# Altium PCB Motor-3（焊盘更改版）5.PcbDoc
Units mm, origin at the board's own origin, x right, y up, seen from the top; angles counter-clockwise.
Board outline 35.05 x 35.13 mm, 4 copper layers (Top1, Signal2, Gnd3, Bottom4), stack 0.778 mm thick; 73 components, 65 nets, 252 pads, 128 vias.
Unrouted connection lines stored in the file: 54.
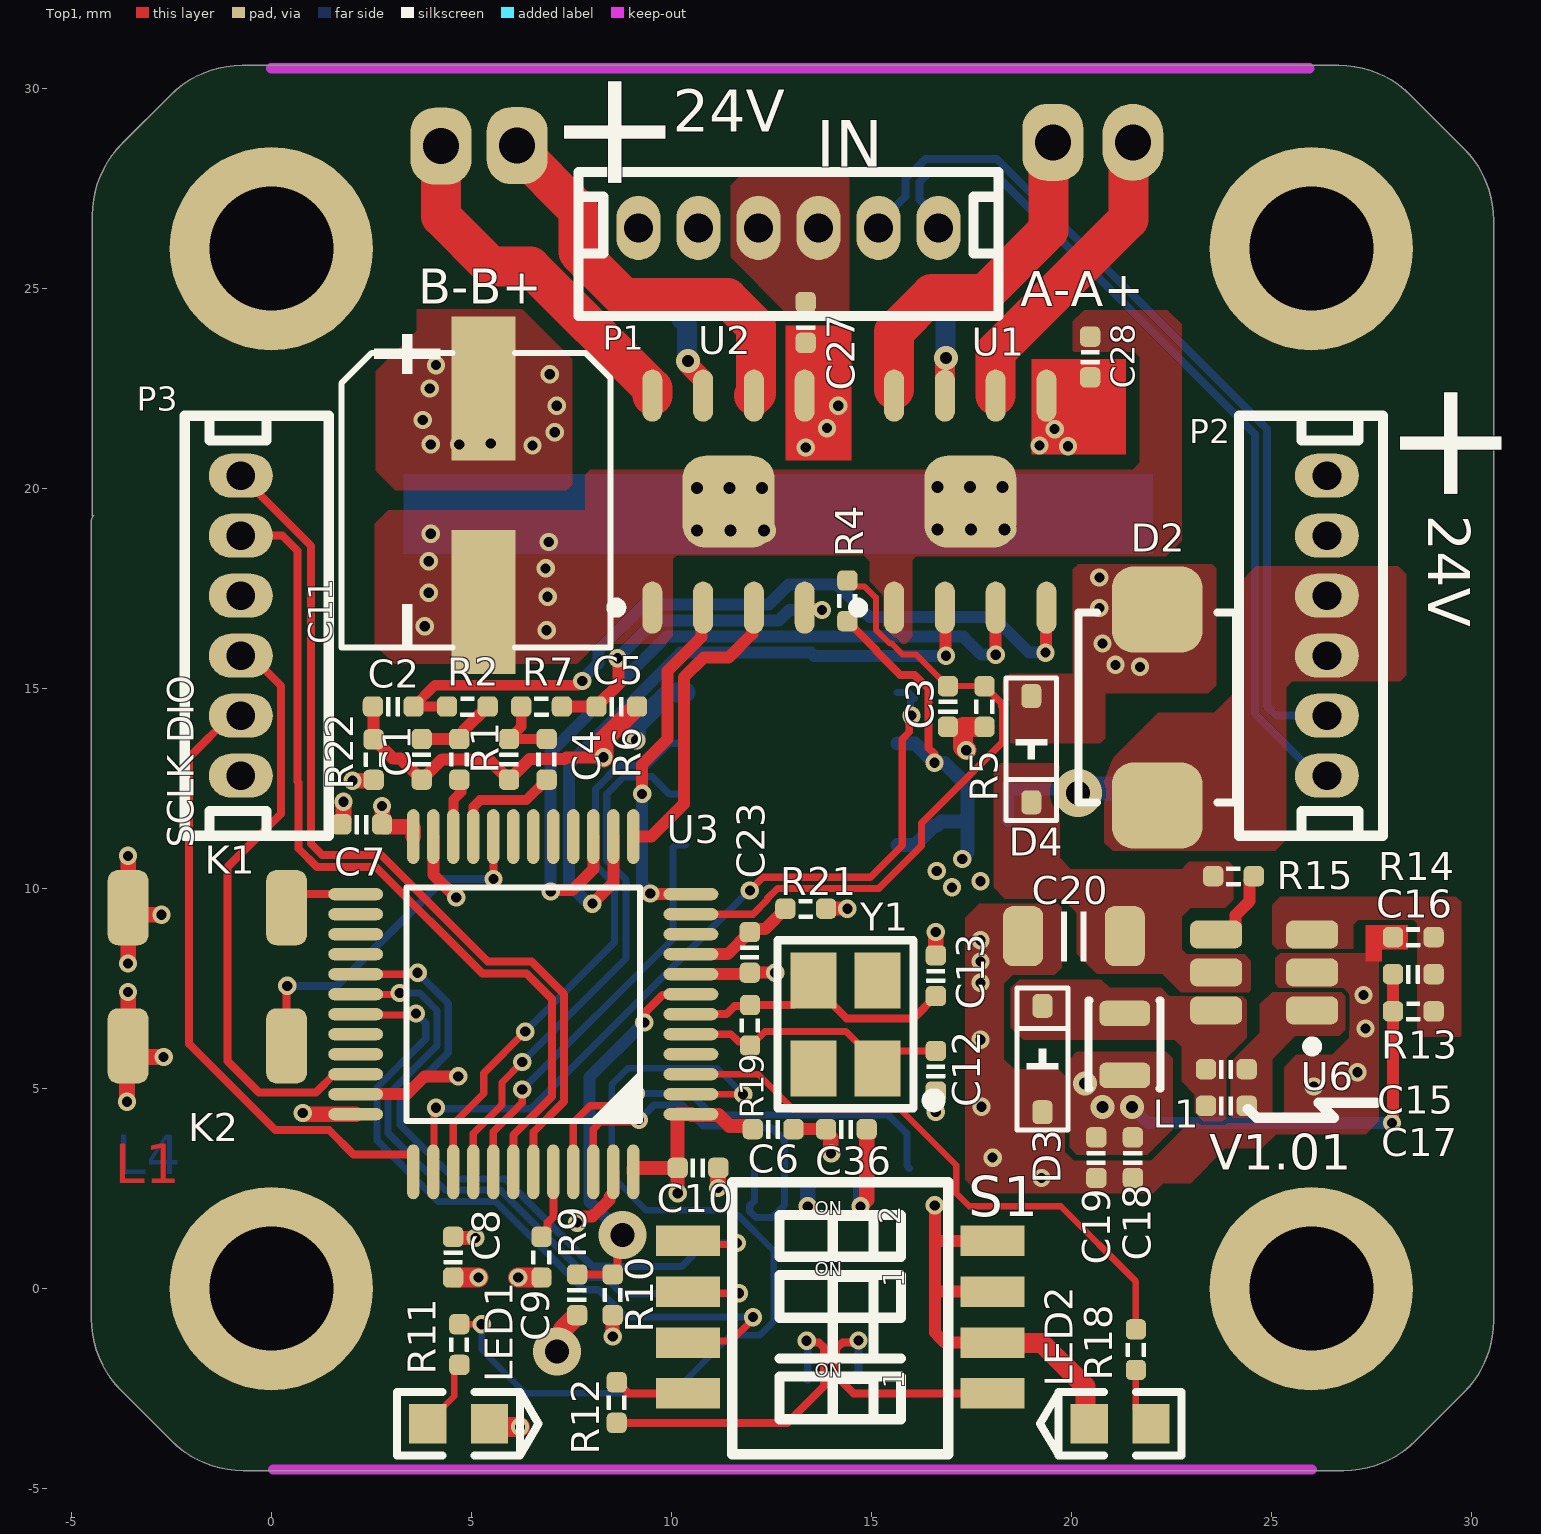
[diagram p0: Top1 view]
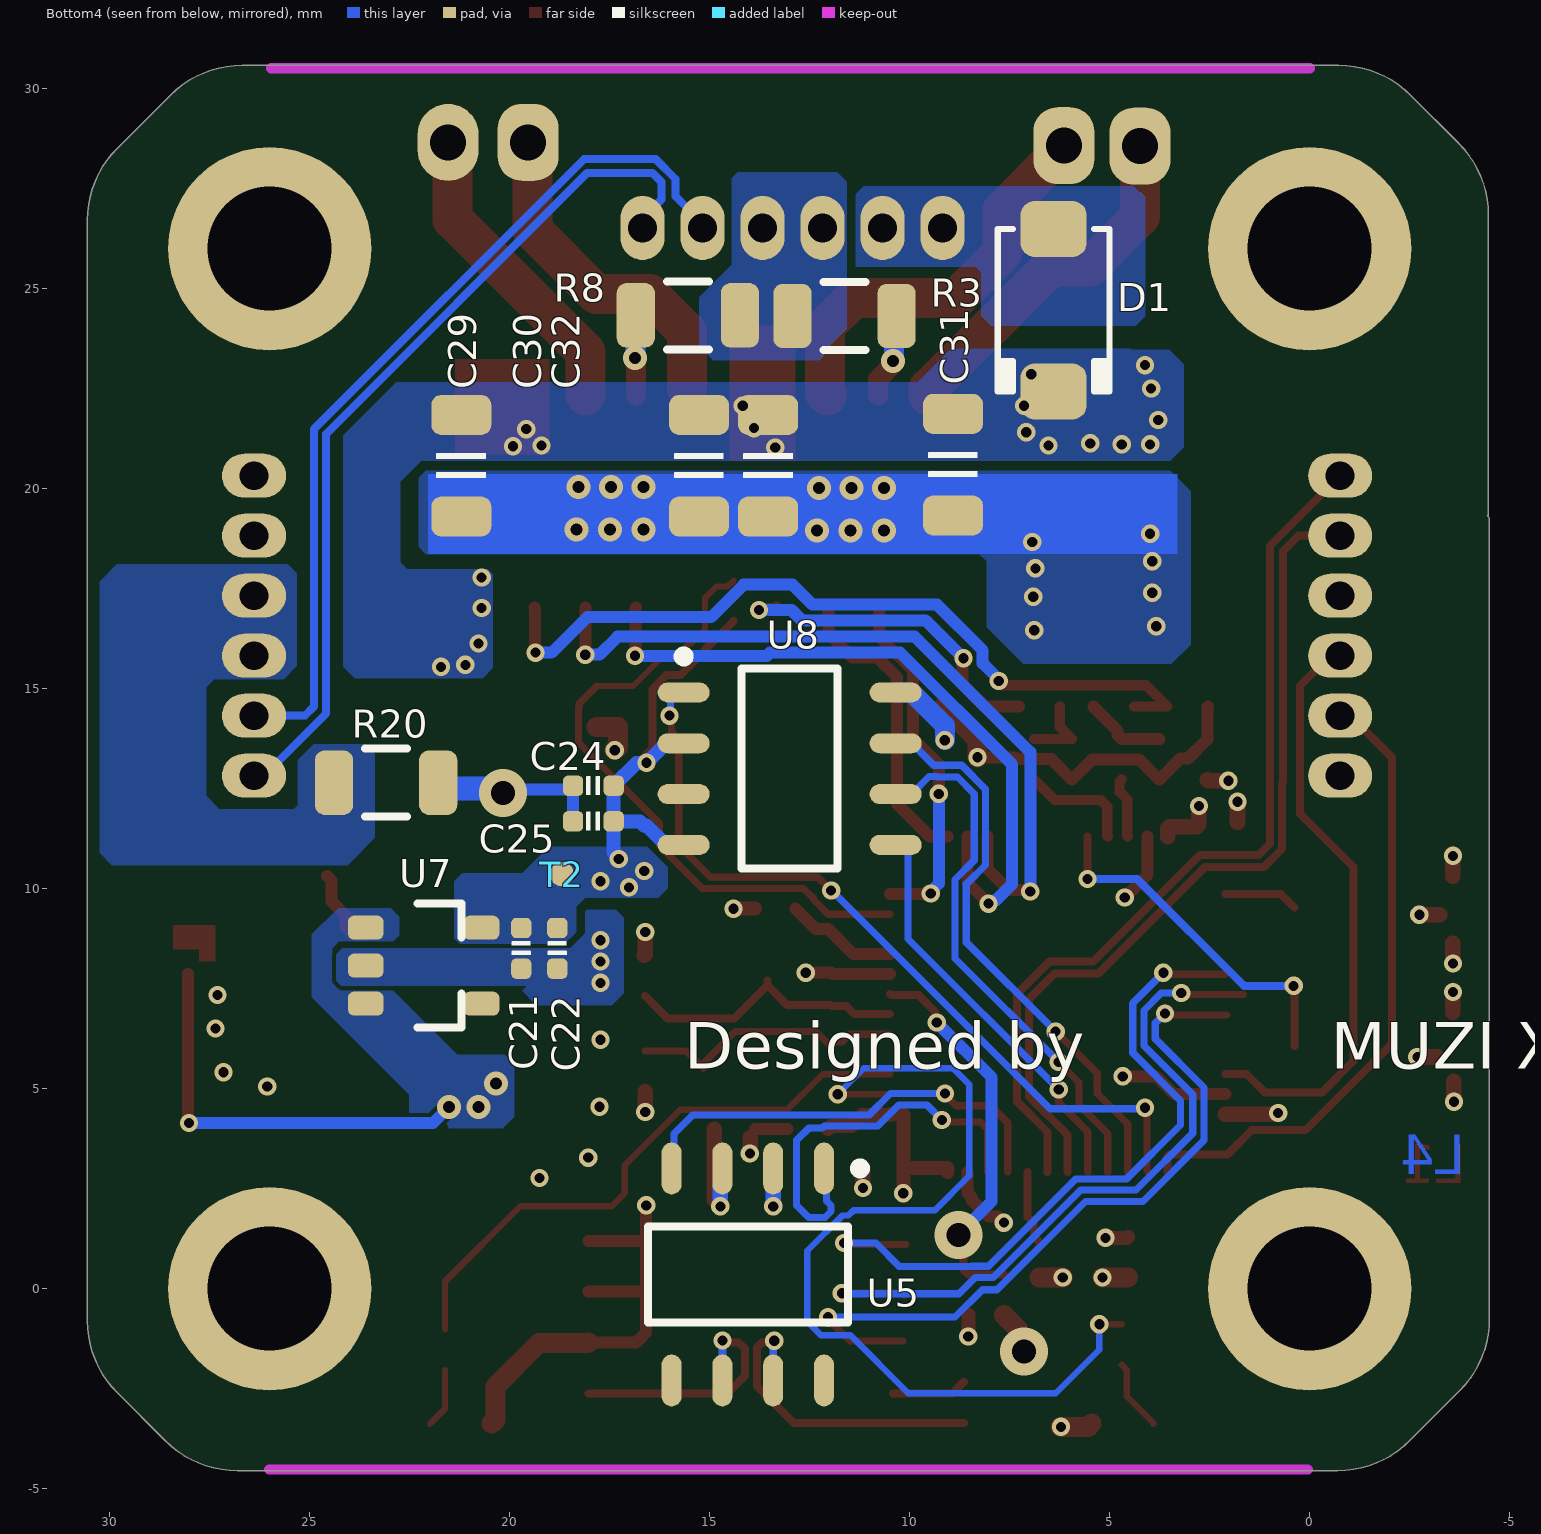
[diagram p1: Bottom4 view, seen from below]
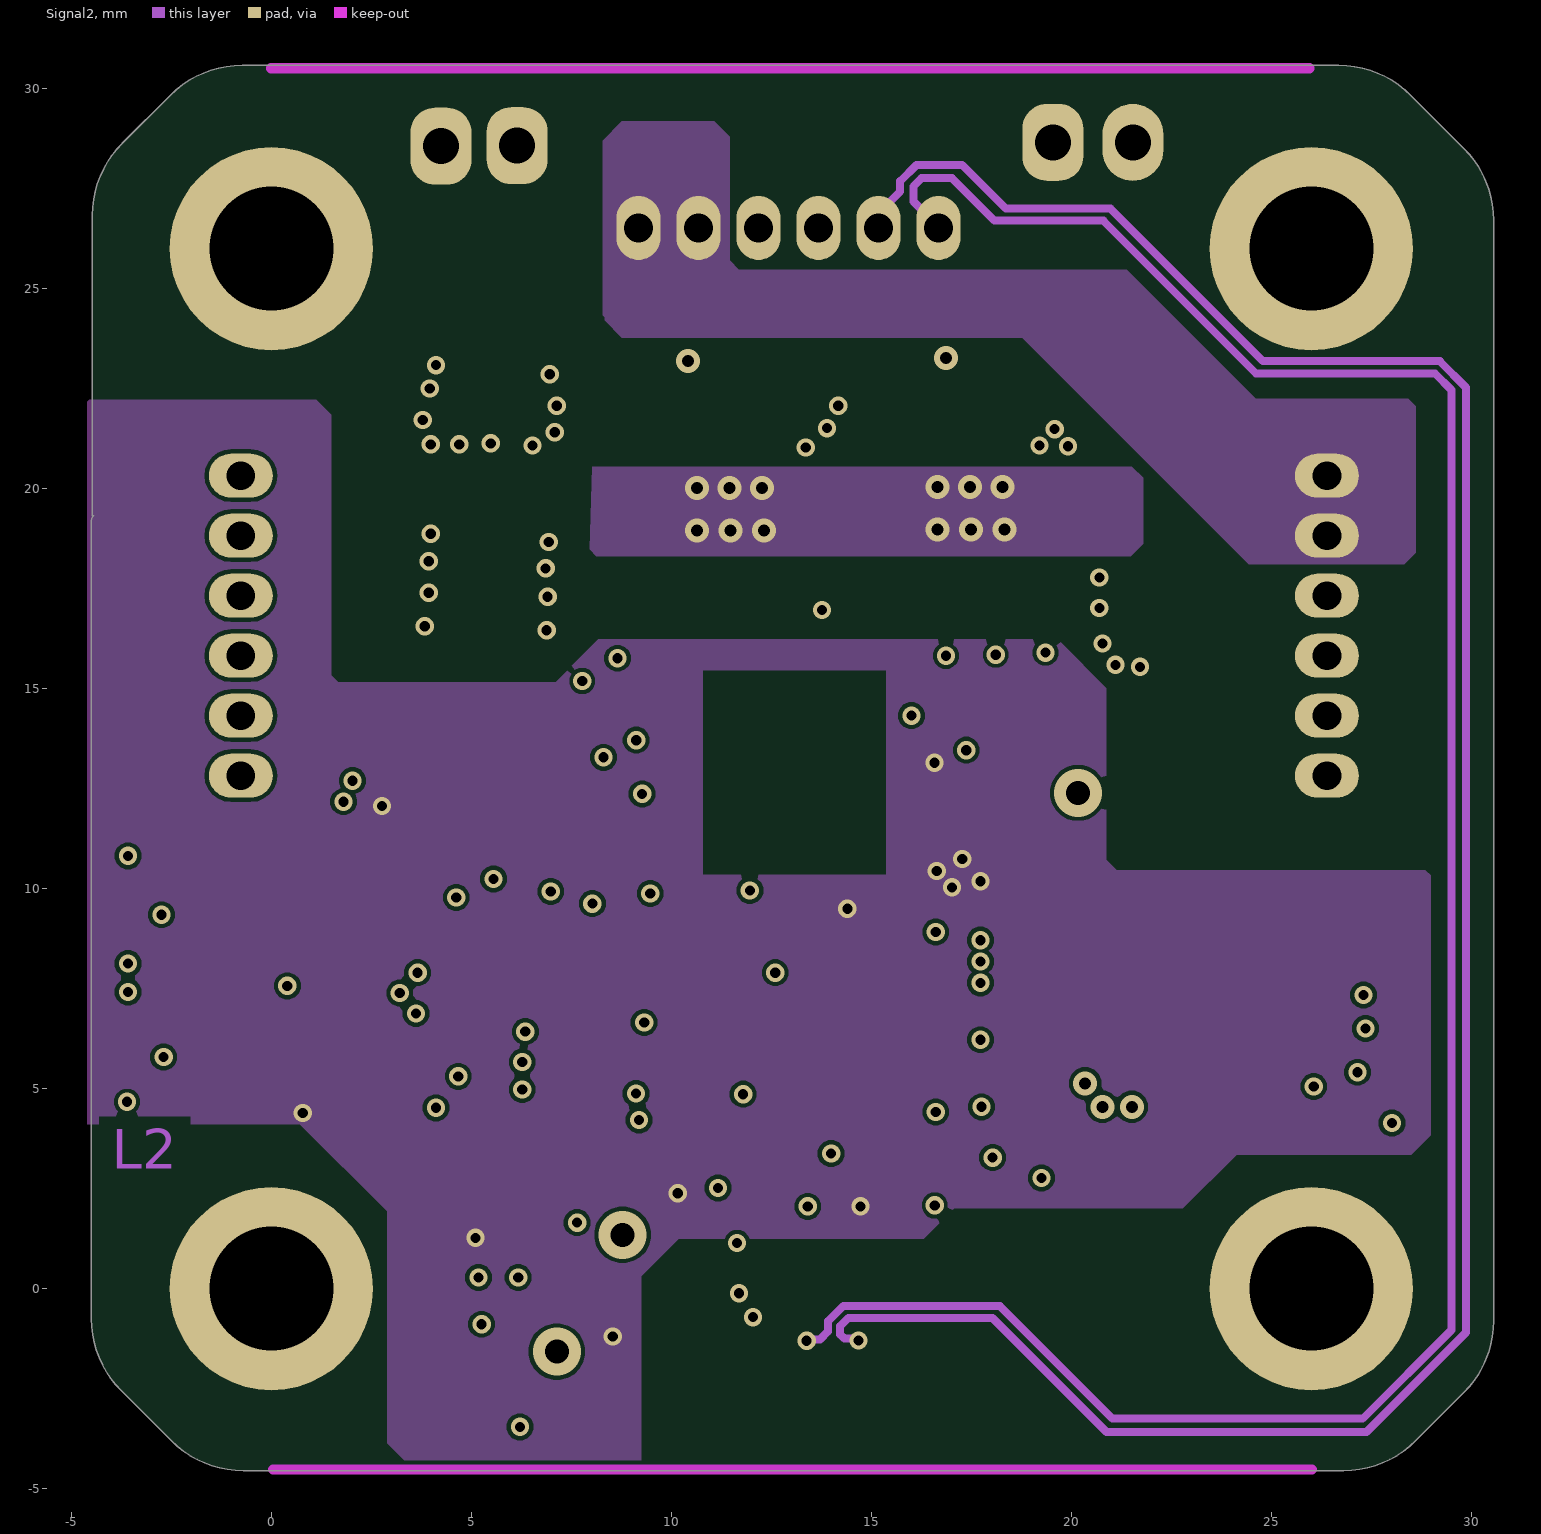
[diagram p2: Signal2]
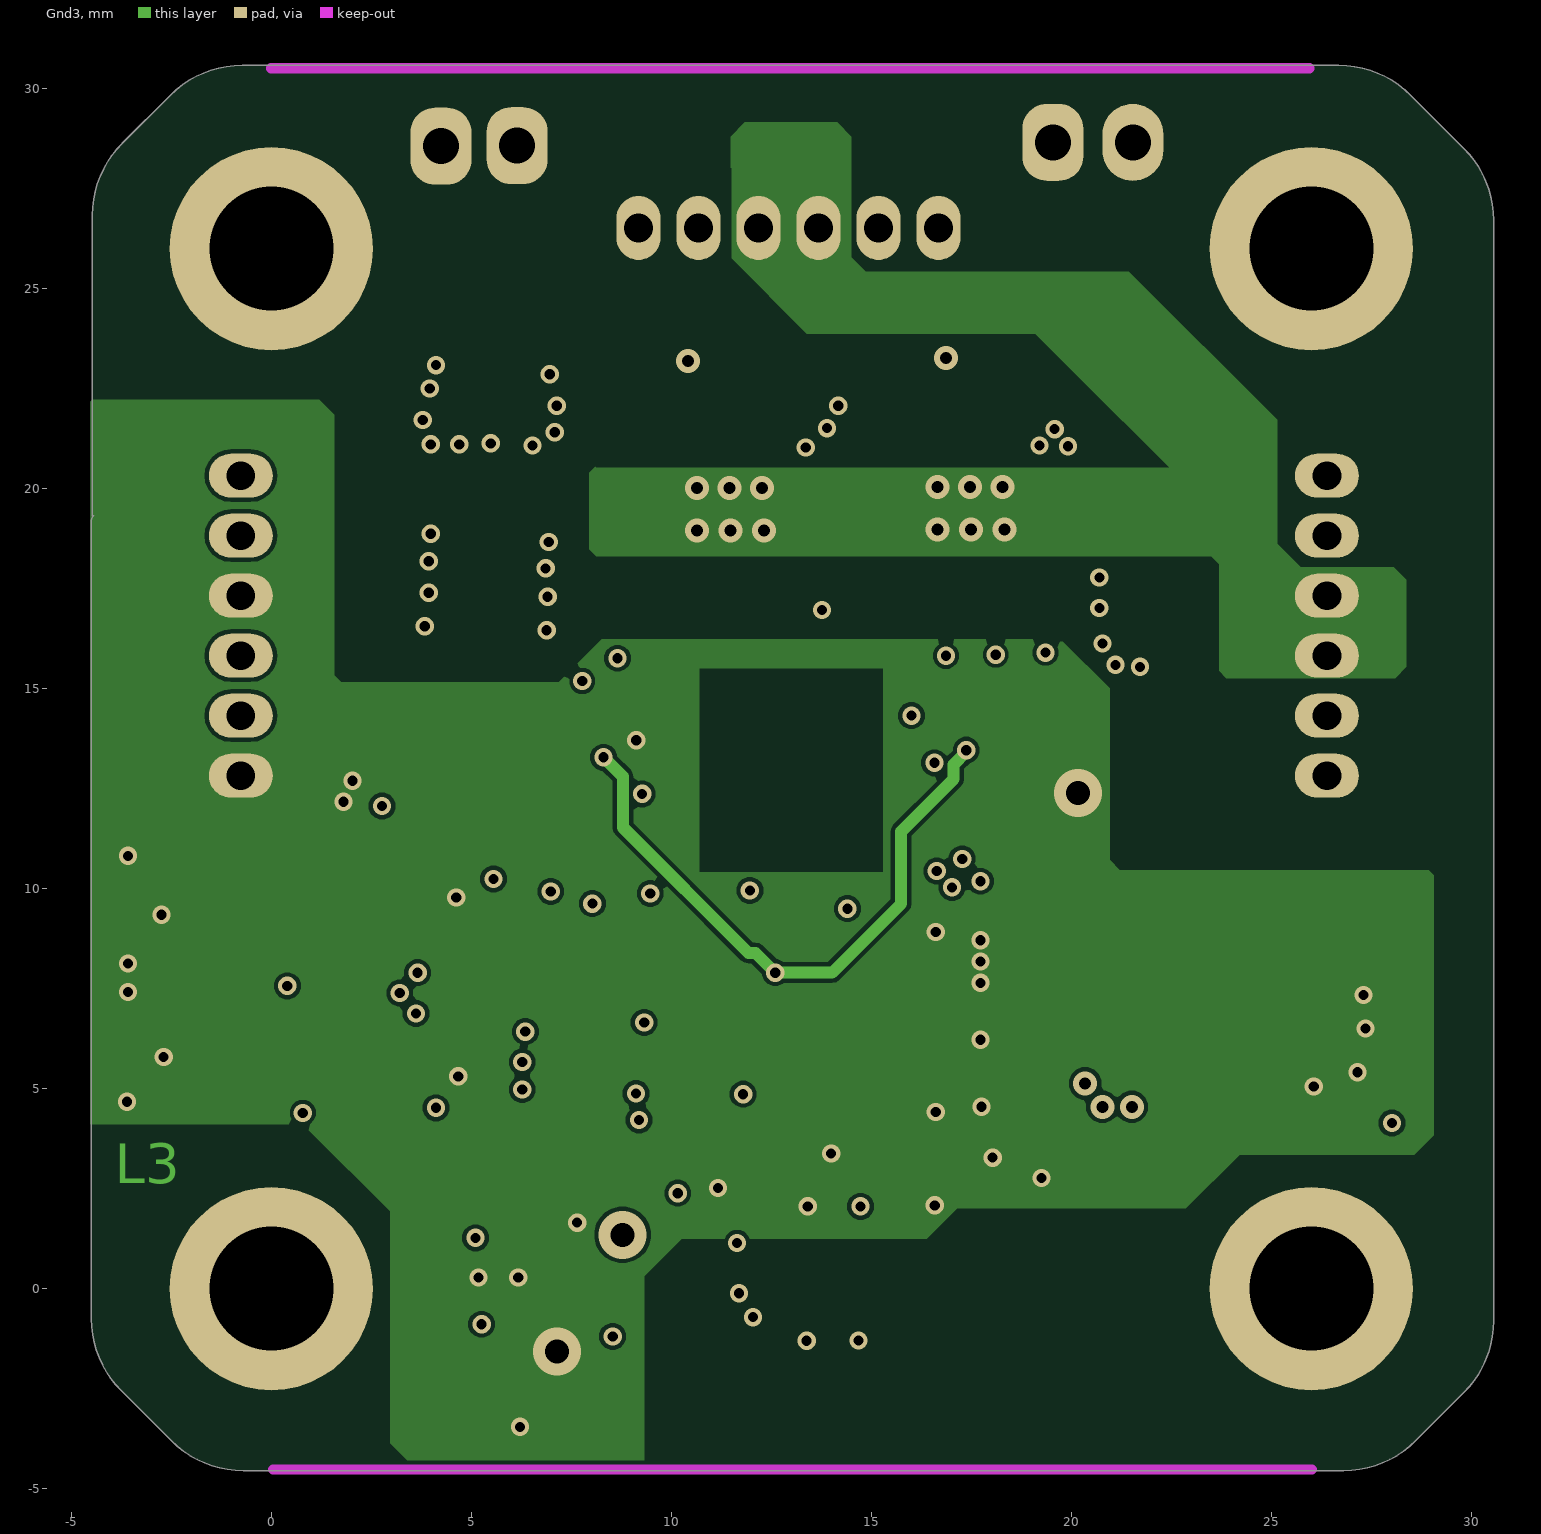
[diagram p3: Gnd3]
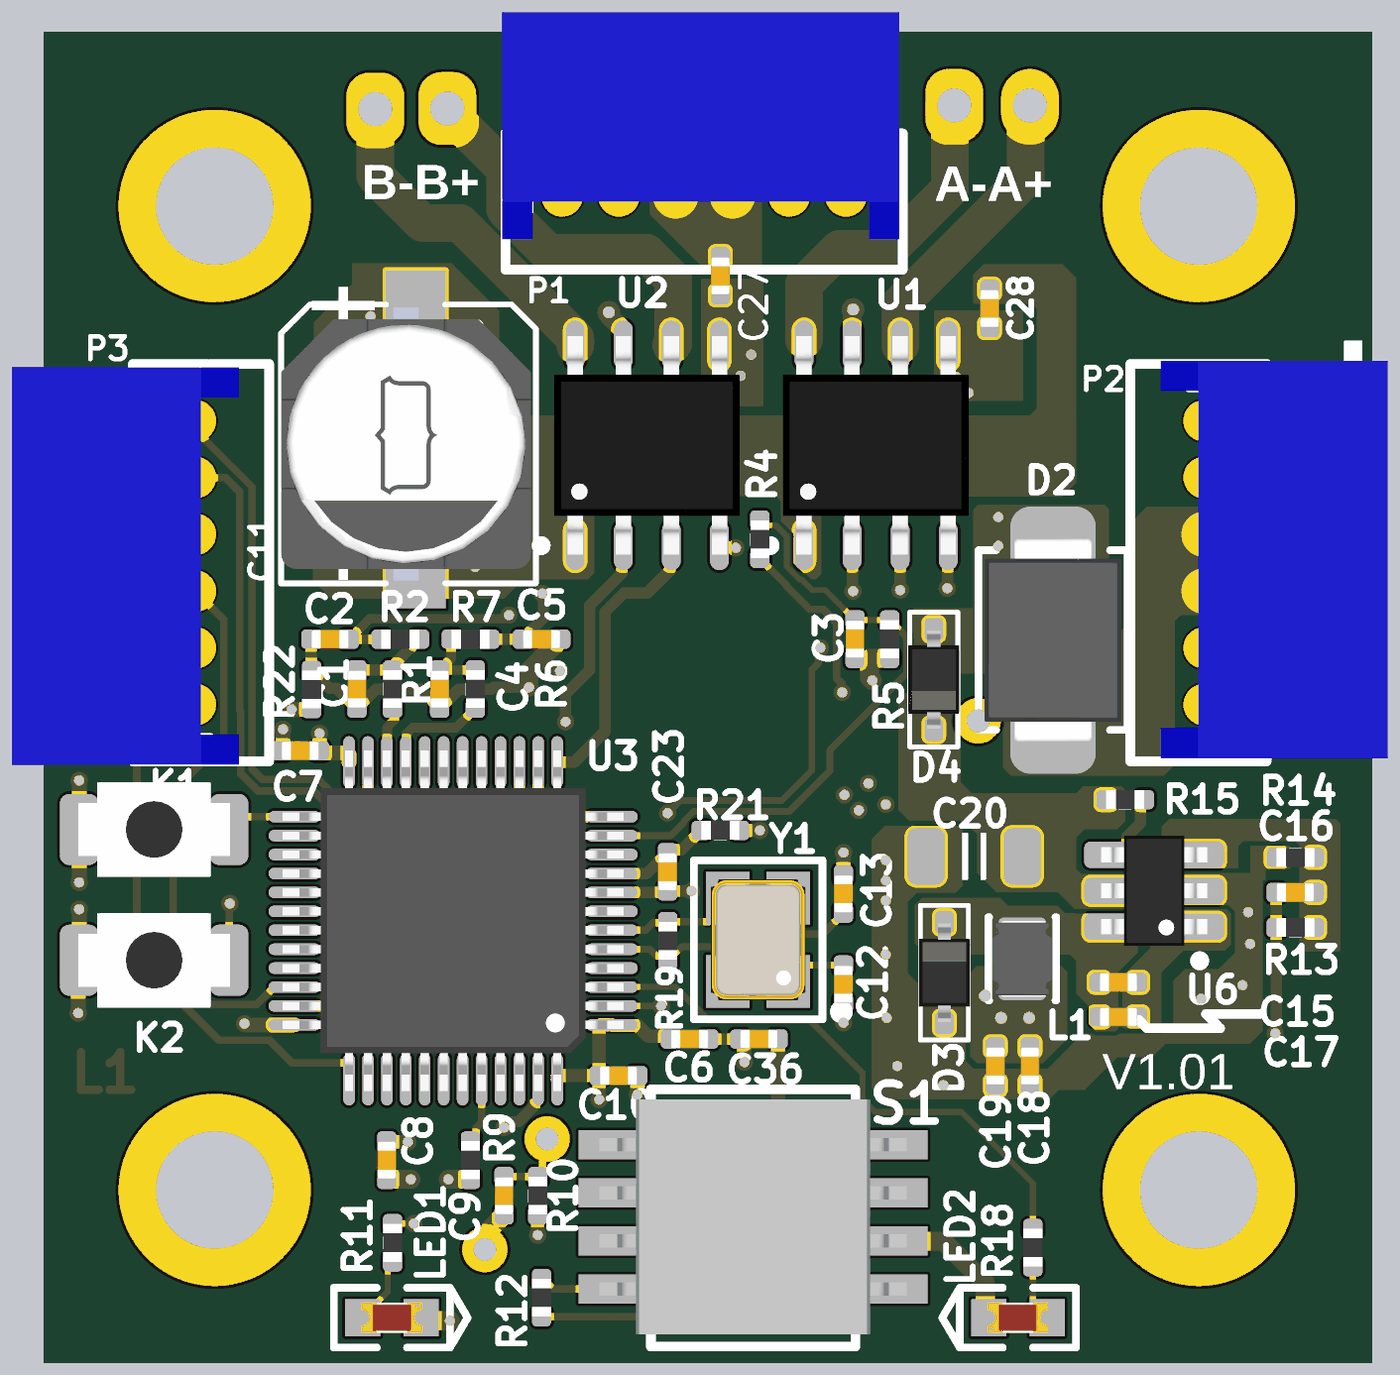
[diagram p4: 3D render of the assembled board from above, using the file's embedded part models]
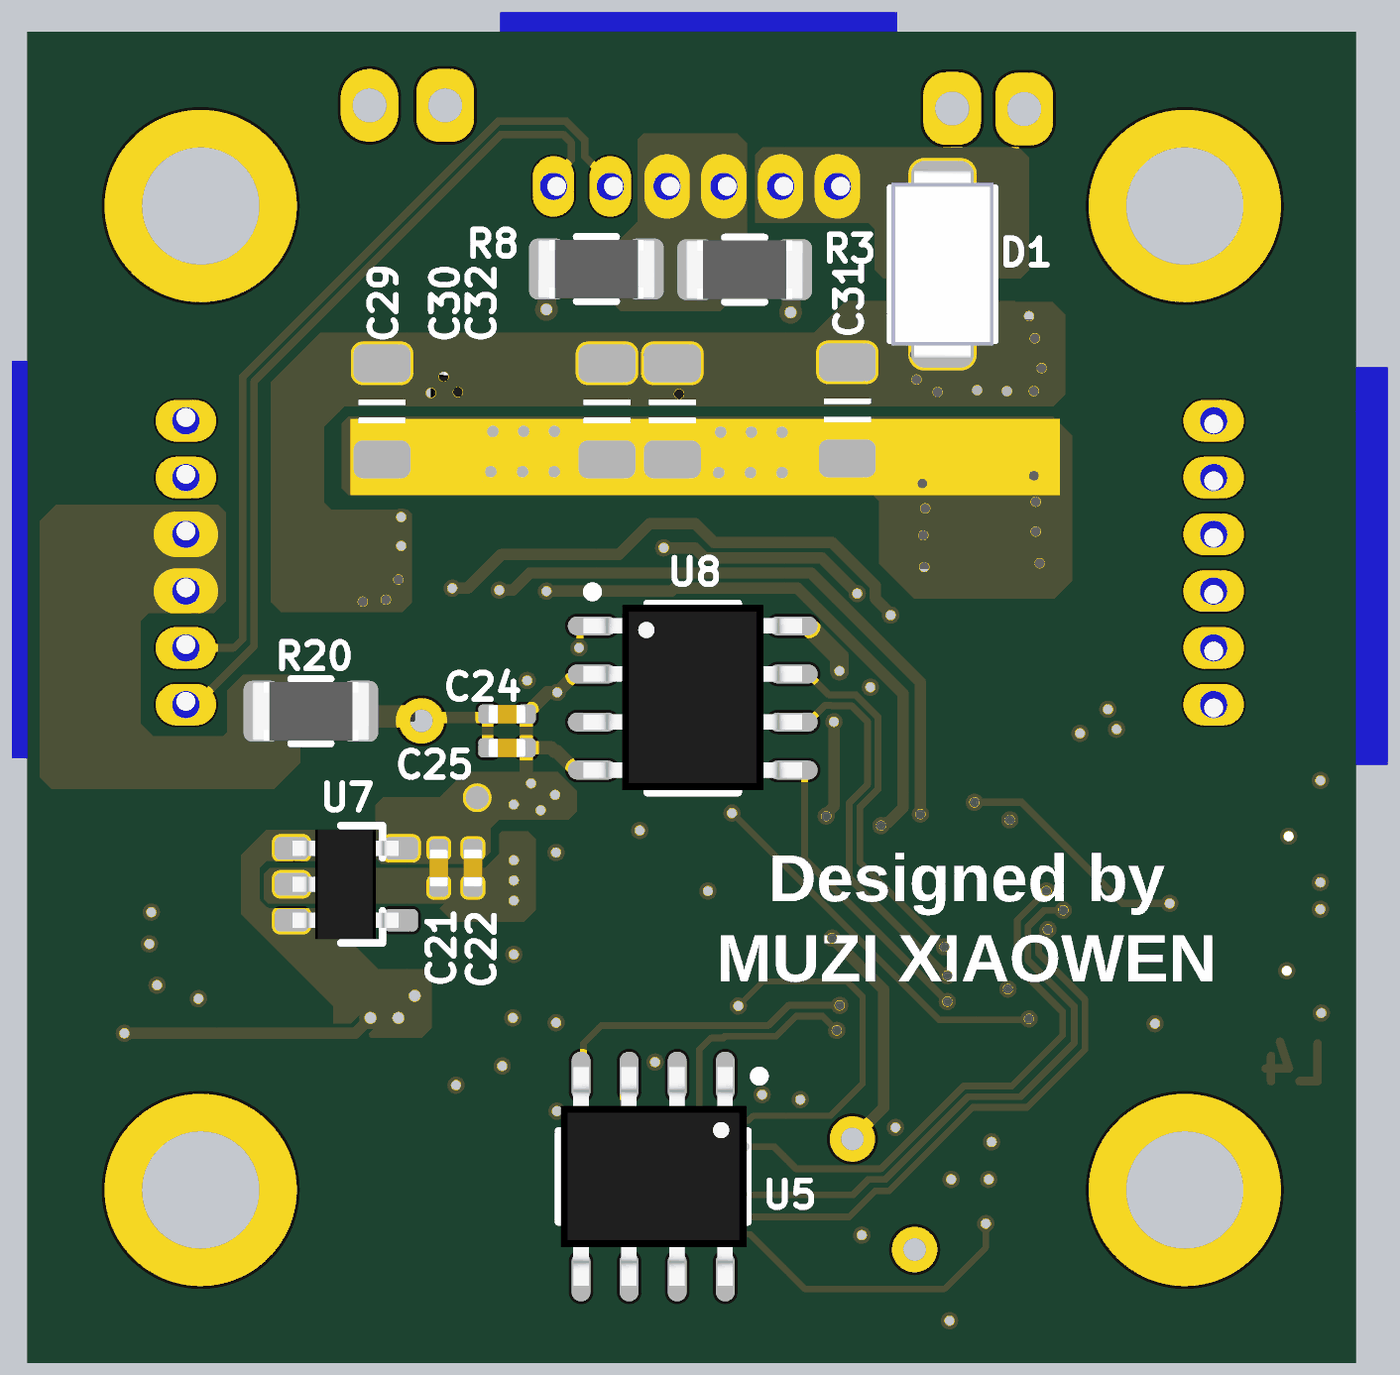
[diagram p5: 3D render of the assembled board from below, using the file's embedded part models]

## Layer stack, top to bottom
Top Solder: solder mask 0.0102, Solder Resist, Dk 3.5
Top1: signal copper 0.0356
Dielectric1: core 0.254, FR-4, Dk 4.2
Signal2: signal copper 0.036
Dielectric2: core 0.254, Dk 4.2
Gnd3: signal copper 0.036
Dielectric3: prepreg 0.127, Dk 4.2
Bottom4: signal copper 0.0356
Bottom Solder: solder mask 0.0102, Solder Resist, Dk 3.5

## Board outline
-4.47,19.329 -4.47,26.837 cw(c-1.93,26.837) -3.726,28.633 -2.522,29.838 cw(c-0.726,28.042) -0.726,30.582 26.685,30.582 cw(c26.685,28.042) 28.481,29.838 29.812,28.506 cw(c28.016,26.71) 30.556,26.71 30.556,-0.802 cw(c28.016,-0.802) 29.812,-2.598 28.608,-3.803 cw(c26.812,-2.007) 26.812,-4.547 -0.7,-4.547 cw(c-0.7,-2.007) -2.497,-3.803 -3.752,-2.547 cw(c-1.956,-0.751) -4.496,-0.751 -4.496,19.207 cw(c-4.322,19.207) -4.445,19.329

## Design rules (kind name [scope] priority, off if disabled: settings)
Clearance [All] p1: gap=0.102 ignorepadtopadclearanceinfootprint=FALSE except(0: Arc-Hole Track-Hole SMDPad-Hole THPad-Hole Via-Hole Fill-Hole Poly-Hole Region-Hole Text-Hole)
ComponentClearance [All] p1: gap=0 collisioncheckmode=3 verticalgap=0 showdistances=FALSE
DiffPairsRouting [All] p1: maxlimit=0.229 minlimit=0.229 mostfreqgap=0.229 toplayer_minwidth=0.381 toplayer_maxwidth=0.381 toplayer_prefwidth=0.381 midlayer1_minwidth=0.381 midlayer1_maxwidth=0.381 midlayer1_prefwidth=0.381 midlayer2_minwidth=0.381 midlayer2_maxwidth=0.381 midlayer2_prefwidth=0.381 bottomlayer_minwidth=0.381 bottomlayer_maxwidth=0.381 bottomlayer_prefwidth=0.381 maxuncoupledlength=12.7
FanoutControl Fanout_BGA [All] p1: bgadir=Out bgaviamode=Centered fanoutstyle=Auto fanoutdirection=Alternating viagrid=0.025 // Fanout_BGA (Default Rule)
HoleSize [All] p1: absolutevalues=TRUE maxlimit=254 minlimit=0.203 maxpercent=80.000 minpercent=20.000
MinimumSolderMaskSliver [All] p1 off: minsoldermaskwidth=0.051
PlaneClearance [All] p1: clearance=0.203
PlaneConnect [All] p1: planeconnectstyle=Direct reliefexpansion=0.508 reliefentries=4 reliefconductorwidth=0.254 reliefairgap=0.254
PolygonConnect [All] p1: connectstyle=Direct reliefconductorwidth=0.254 reliefentries=4 polygonreliefangle="90 Angle" airgapwidth=0.254
RoomDefinition Port [InComponentClass('Port')] p1 off: confinementstyle=ConfineIn formatcopy=TRUE lockcomponents=FALSE outline -13.335,-36.017 37.465,-36.017 37.465,-10.617 -13.335,-10.617
RoomDefinition MCU [InComponentClass('MCU')] p2 off: confinementstyle=ConfineIn formatcopy=TRUE lockcomponents=FALSE outline -13.233,-36.17 37.567,-36.17 37.567,-10.77 -13.233,-10.77
RoomDefinition Interface [InComponentClass('Interface')] p3 off: confinementstyle=ConfineIn formatcopy=TRUE lockcomponents=FALSE outline -14.453,-36.5 36.347,-36.5 36.347,-11.1 -14.453,-11.1
RoomDefinition Drive [InComponentClass('Drive')] p4 off: confinementstyle=ConfineIn formatcopy=TRUE lockcomponents=FALSE outline -13.005,-36.5 37.795,-36.5 37.795,-11.1 -13.005,-11.1
RoomDefinition Power [InComponentClass('Power')] p5 off: confinementstyle=ConfineIn formatcopy=TRUE lockcomponents=FALSE outline -12.675,-36.144 38.125,-36.144 38.125,-10.744 -12.675,-10.744
RoutingVias [All] p1: holewidth=0.203 width=0.406 viastyle="Through Hole" minholewidth=0.152 minwidth=0.305 maxholewidth=0.711 maxwidth=1.27
SilkToSilkClearance [All] p1: silktosilkclearance=0
SilkToSolderMaskClearance [IsPad] p1: minsilkscreentomaskgap=0 clearancetoexposedcopper=TRUE
SolderMaskExpansion [All] p1: expansion=0.076 istentingtop=FALSE
Width GND [(InNet('AGND') OR InNet('GND'))] p1: maxlimit=1.27 minlimit=0.102 preferedwidth=0.254
Width VCC [(InNet('VDD_SYS_3.3V') OR InNet('VDD_AV_3.3V') OR InNet('VDD_5V') OR InNet('VDD1V2-SYS') OR InNet('VDD1V1-EPHY') OR InNet('VDD-CPUX') OR InNet('VDD-CPUS') OR InNet('VDD-CPUFB') OR InNet('VCC-DRAM'))] p2: maxlimit=1.27 minlimit=0.102 preferedwidth=0.254
Width [All] p3: maxlimit=254 minlimit=0.102 preferedwidth=0.102
21 further rules are at their usual default settings.

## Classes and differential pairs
component class Port: C36 K1 K2 P1 P2 P3 R12 S1 U5
component class MCU: C6 C7 C8 C9 C10 C12 C13 C23 LED1 LED2 R9 R10 R11 R18 R19 R21 R22 U3 Y1
component class Interface: C24 C25 U8
component class Drive: C1 C2 C3 C4 C5 C27 C28 R1 R2 R3 R4 R5 R6 R7 R8 R20 U1 U2
component class Power: C11 C15 C16 C17 C18 C19 C20 C21 C22 C29 C30 C31 C32 D1 D2 D3 D4 L1 R13 R14 R15 T2 U6 U7

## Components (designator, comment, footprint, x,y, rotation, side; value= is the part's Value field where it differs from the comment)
C1 "0.1uF" CAP_0402 3.759,13.233 r90 top value=0.1u
C2 "0.1uF" CAP_0402 3.048,14.554 r0 top value=0.1u
C3 "10uF" CAP_0402 16.916,14.554 r90 top value=0.1u
C4 "0.1uF" CAP_0402 5.944,13.233 r90 top value=0.1u
C5 "0.1uF" CAP_0402 8.636,14.554 r180 top value=0.1u
C6 "0.1uF" CAP_0402 12.548,3.988 r180 top value=0.1u
C7 "0.1uF" CAP_0402 2.261,11.608 r0 top value=0.1u
C8 "0.1uF" CAP_0402 4.547,0.787 r90 top value=0.1u
C9 "0.1uF" CAP_0402 7.645,-0.152 r90 top value=0.1u
C10 "10uF" CAP_0402 10.668,3.023 r180 top value=0.1u
C11 "220uF/25V" CAP-SMD_BD8.0-L8.3-W8.3-LS9.3-FD 5.309,19.964 r270 top locked value=150uF/35V
C12 "20pF" CAP_0402 16.612,5.436 r270 top
C13 "20pF" CAP_0402 16.612,7.823 r90 top
C15 "0.1uF" CAP_0402 23.876,5.486 r0 top value=0.1u
C16 "100pF" CAP_0402 28.55,7.861 r0 top value=0.1u
C17 "0.1uF" CAP_0402 23.876,4.572 r0 top value=0.1u
C18 "0.1uF" CAP_0402 21.539,3.277 r90 top value=0.1u
C19 "10uF" CAP_0402 20.625,3.277 r90 top value=0.1u
C20 "10uF/50V" 1206-CAP 20.066,8.814 r0 top value=0.1u
C21 "0.1uF" CAP_0402 19.71,8.509 r90 bottom value=0.1u
C22 "10uF" CAP_0402 18.809,8.509 r90 bottom value=0.1u
C23 "0.1uF" CAP_0402 11.963,8.407 r90 top value=0.1u
C24 "10uF" CAP_0402 17.907,12.573 r180 bottom value=0.1u
C25 "0.1uF" CAP_0402 17.907,11.684 r180 bottom value=0.1u
C27 "0.1uF" CAP_0402 13.36,24.155 r270 top value=0.1u
C28 "0.1uF" CAP_0402 20.472,23.292 r270 top value=0.1u
C29 "10uF/50V" 1206-CAP 21.209,20.574 r270 bottom
C30 "10uF/50V" 1206-CAP 15.265,20.574 r270 bottom
C31 "10uF/50V" 1206-CAP 8.915,20.599 r270 bottom
C32 "10uF/50V" 1206-CAP 13.538,20.574 r270 bottom
C36 "0.1uF" CAP_0402 14.376,3.988 r0 top value=0.1u
D1 "SS54" DO-214AC 6.401,24.46 r270 bottom
D2 "SMBJ28CA" SMBJ-CA_MFG 22.149,14.529 r90 top
D3 "二极管-5819W" SOD-323 19.279,5.74 r90 top
D4 "二极管-5819W" SOD-323 18.999,13.487 r270 top
K1 "TACT 2P" ButtonTACT_3x4x2_180 -1.6,9.525 r0 top value=3x4
K2 "TACT 2P" ButtonTACT_3x4x2_180 -1.6,6.071 r0 top value=3x4
L1 "6.8uH" IND-201612 21.336,6.108 r270 top
LED1 "LED GREEN" LED-0603 4.693,-3.423 r180 top
LED2 "LED GREEN" LED-0603 21.209,-3.327 r0 top
P1 "Header 6H" CONN-TH_HC-ZH1.5-6A-s 12.929,26.518 r0 top locked
P2 "Header 6H" CONN-TH_HC-ZH1.5-6A-s 26.391,16.574 r270 top
P3 "Header 6H" CONN-TH_HC-ZH1.5-6A-s -0.762,16.574 r90 top
R1 "1K" RES_0402 4.699,13.233 r90 top value=22R
R2 "1K" RES_0402 4.902,14.554 r180 top value=22R
R3 "0.1R" 1206-RES 15.545,24.333 r180 bottom value=22R
R4 "NCP15XH103F03RC" RES_0402 14.402,17.196 r270 top value=10k
R5 "3.3K" RES_0402 17.831,14.554 r90 top value=22R
R6 "1K" RES_0402 6.883,13.233 r90 top value=22R
R7 "1K" RES_0402 6.756,14.554 r0 top value=22R
R8 "0.1R" 1206-RES 11.627,24.318 r0 bottom value=22R
R9 "10K" RES_0402 6.756,0.787 r270 top value=22R
R10 "10K" RES_0402 8.534,-0.152 r270 top value=22R
R11 "1K" RES_0402 4.699,-1.397 r270 top value=22R
R12 "120R" RES_0402 8.636,-2.845 r90 top value=22R
R13 "10K" RES_0402 28.55,6.934 r180 top value=22R
R14 "1.8K" RES_0402 28.55,8.788 r0 top value=22R
R15 "1M" RES_0402 24.054,10.312 r0 top value=22R
R18 "1K" RES_0402 21.615,-1.524 r270 top value=22R
R19 "1M" RES_0402 11.969,6.585 r270 top value=22R
R20 "0R" 1206-RES 23.089,12.649 r0 bottom
R21 "0" RES_0402 13.36,9.5 r0 top value=0R
R22 "0" RES_0402 2.559,13.227 r90 top value=0R
S1 "DSHP04TSGER" SW-SMD_DSHP04TS-S 10.414,-0.076 r90 top
T2 "测试点" TEST_PT 18.694,10.363 r90 bottom
U1 "TB67H450FNG" SO-8-PAD 17.475,19.677 r0 top locked
U2 "TB67H450FNG" SO-8-PAD 11.43,19.677 r0 top locked
U3 "STM32F103CBT6" LQFP-48 6.299,7.112 r0 top locked
U5 "SN65HVD232D" so-8 14.046,0.356 r90 bottom
U6 "ME3116" SOT23-6 24.822,7.905 r90 top
U7 "LP2992 3V3" SOT23-5 22.098,8.077 r270 bottom
U8 "MT6816" SO-8 13,13 r180 bottom locked
Y1 "XTAL-4" LC-SMD-3225_4P 14.357,6.61 r90 top locked value="12 MHz"

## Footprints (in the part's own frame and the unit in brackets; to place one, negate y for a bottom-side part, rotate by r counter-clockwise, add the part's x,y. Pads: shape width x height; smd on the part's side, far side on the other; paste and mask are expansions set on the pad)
1206-CAP [mm]
  rrect50% 1x1.5 smd: 1(-1.27,0) 2(1.27,0)
  silkscreen extent -0.3,-0.61 0.3,0.61, body extent -1.5,-0.75 1.5,0.75, height 1.5
1206-RES [mm]
  rrect50% 0.956x1.61 smd paste+0 mask+0: 1(-1.301,0) 2(1.301,0)
  silkscreen extent -0.52,-0.85 0.52,0.85, body extent -1.55,-0.77 1.55,0.77, height 0.65
ButtonTACT_3x4x2_180 [mil]
  rrect50% 40x74 smd: 1(-78,0) 2(78,0)
  body extent -79,-49 79,49, height 63
CAP-SMD_BD8.0-L8.3-W8.3-LS9.3-FD [mm]
  rect 3.6x1.6 smd: 1(-2.54,0) 2(2.794,0)
  silkscreen extent -3.9,-3.56 3.94,3.18, body extent -3.35,-3.55 3.85,3.05, height 7.7
CAP_0402 [mil]
  rrect50% 20x20 smd: 1(-20,0) 2(20,0)
  silkscreen extent -7,-9 7,9, body extent -20,-10 20,10, height 20
CONN-TH_HC-ZH1.5-6A-s [mm]
  oval 1.1x1.6 hole 0.72 paste+0 mask+0.05: 1(-3.75,0) 2(-2.25,0) 3(-0.75,0) 4(0.75,0) 5(2.25,0) 6(3.75,0)
  silkscreen extent -5.25,-2.2 5.25,1.4, body extent -5.34,-1.4 5.16,4.6, height 4
DO-214AC [mil] "SMA"
  rrect50% 55x65 smd: 1(-80,0) 2(80,0)
  silkscreen extent -80,-55 80,55, body extent -98,-53 98,53, height 85
IND-201612 [mm]
  rrect50% 0.635x1.27 smd paste+0 mask+0: 1(-0.774,0) 2(0.774,0)
  silkscreen extent -1.1,-0.9 1.1,0.9, body extent -1,-0.8 1,0.8, height 0.95
LC-SMD-3225_4P [mm]
  rect 1.4x1.15 smd: 1(-1.1,-0.8) 2(1.1,-0.8) 3(1.1,0.8) 4(-1.1,0.8)
  silkscreen extent -2.1,-2.35 2.1,1.7, body extent -1.6,-1.25 1.6,1.25, height 0.61
LED-0603 [mm]
  rect 0.93x0.98 smd: A(0.782,-0.048) C(-0.758,-0.048)
  silkscreen extent -1.99,-0.84 1.55,0.74, body extent -0.79,-0.45 0.81,0.35, height 0.6
LQFP-48 [mil]
  oval 54x12 smd: 1(165,-108.27) 2(165,-88.58) 3(165,-68.9) 4(165,-49.21) 5(165,-29.53) 6(165,-9.84) 7(165,9.84) 8(165,29.53) 9(165,49.21) 10(165,68.9) 11(165,88.58) 12(165,108.27) 25(-165,108.27) 26(-165,88.58) 27(-165,68.9) 28(-165,49.21) 29(-165,29.53) 30(-165,9.84) 31(-165,-9.84) 32(-165,-29.53) 33(-165,-49.21) 34(-165,-68.9) 35(-165,-88.58) 36(-165,-108.27)
  oval 12x54 smd: 13(108.27,165) 14(88.58,165) 15(68.9,165) 16(49.21,165) 17(29.53,165) 18(9.84,165) 19(-9.84,165) 20(-29.53,165) 21(-49.21,165) 22(-68.9,165) 23(-88.58,165) 24(-108.27,165) 37(-108.27,-165) 38(-88.58,-165) 39(-68.9,-165) 40(-49.21,-165) 41(-29.53,-165) 42(-9.84,-165) 43(9.84,-165) 44(29.53,-165) 45(49.21,-165) 46(68.9,-165) 47(88.58,-165) 48(108.27,-165)
  silkscreen extent -115,-115 115,115, body extent -177,-177 177,177, height 61
RES_0402 [mil]
  rrect50% 20x20 smd: 1(-20,0) 2(20,0)
  silkscreen extent -7,-10 7,10, body extent -20,-10 20,10, height 14
SMBJ-CA_MFG [mm]
  rrect50% 2.16x2.26 smd paste+0 mask+0: 1(-2.45,0) 2(2.45,0)
  silkscreen extent -2.37,-1.97 2.37,1.97, body extent -2.7,-1.81 2.7,1.81, height 2.62
so-8 [mm]
  oval 1.3x0.5 smd: 1(2.65,-1.905) 2(2.65,-0.635) 3(2.65,0.635) 4(2.65,1.905) 5(-2.65,1.905) 6(-2.65,0.635) 7(-2.65,-0.635) 8(-2.65,-1.905)
  silkscreen extent -1.2,-2.93 2.77,2.5, body extent -2.89,-2.46 2.89,2.44, height 1.45
SO-8 [mm]
  oval 1.3x0.5 smd: 1(-2.65,1.905) 2(-2.65,0.635) 3(-2.65,-0.635) 4(-2.65,-1.905) 5(2.65,-1.905) 6(2.65,-0.635) 7(2.65,0.635) 8(2.65,1.905)
  silkscreen extent -2.78,-2.5 1.2,2.93, body extent -2.89,-2.44 2.89,2.46, height 1.45
SO-8-PAD [mm]
  oval 0.5x1.3 smd: 1(-1.905,-2.65) 2(-0.635,-2.65) 3(0.635,-2.65) 4(1.905,-2.65) 5(1.905,2.65) 6(0.635,2.65) 7(-0.635,2.65) 8(-1.905,2.65)
  rrect50% 2.3x2.3 smd: 9(0,0)
  silkscreen extent -2.93,-2.77 -2.68,-2.53, body extent -2.46,-2.89 2.44,2.89, height 1.45
SOD-323 [mm]
  rrect50% 0.6x0.5 smd: 1(-1.329,0) 2(1.329,0)
  silkscreen extent -1.78,-0.64 1.78,0.64, body extent -1.3,-0.68 1.3,0.67, height 1.15
SOT23-5 [mm] "SOT23, 3-Leads, Body 3.1x3.0mm (max), Pitch 0.95mm, IPC Medium Density"
  rrect50% 0.6x0.889 smd: 1(-0.95,-1.5) 2(0,-1.5) 3(0.95,-1.5) 4(0.95,1.396) 5(-0.95,1.396)
  silkscreen extent -1.55,-0.2 1.55,0.9, body extent -1.45,-1.48 1.45,1.32, height 1.2
SOT23-6 [mm]
  rrect50% 0.7x1.3 smd: 1(-0.95,-1.2) 2(0,-1.2) 3(0.95,-1.2) 4(0.95,1.2) 5(0,1.2) 6(-0.95,1.2)
  silkscreen extent -1.97,-1.33 -1.73,-1.08, body extent -1.45,-1.4 1.45,1.4, height 1.45
SW-SMD_DSHP04TS-S [mm]
  rect 0.762x1.6 smd: 1(1.27,0) 2(0,0) 3(-1.27,0) 4(-2.54,0) 5(-2.54,-7.62) 6(-1.27,-7.62) 7(0,-7.62) 8(1.27,-7.62)
  silkscreen extent -4.06,-6.51 2.73,-1.11, body extent -3.73,-7.87 2.46,0.25, height 1.71
TEST_PT [mm]
  rrect100% 0.606x0.606 smd: 0(0,0)

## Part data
C1 C2 C3 C4 C5 C6 C7 C8 C9 C10 C12 C13 C15 C16 C17 C18 C19 C20 C21 C22 C23 C24 C25 C27 C28 C36: library part 电容-0402, "Capacitor"
C11 C29 C30 C31 C32: library part CAP, "Capacitor, chip, ceramic"
D1: library part Diode_SMA, "Diode"
D3 D4: "40V"
K1 K2: library part ButtonTACT_3x4x2_180, "Button"
L1: library part 电感-201612
LED1 LED2: library part LED, "LED GRN SGL RA 25mA 4.1V SMD"
P1 P2 P3: "Header, 6-Pin, Right Angle"
R1 R2 R5 R6 R7 R9 R10 R11 R12 R13 R14 R15 R18 R19 R21 R22: library part 电阻-0402, "Resistor"
R3 R8 R20: library part 电阻-1206, "Resistor"
R4: "THERMISTOR 10K OHM NTC 0402 SMD"
S1: library part 218-4LPSTJ, "DIP Switches / SIP Switches 4 pos. low profile Btm Seal Tape J Bend", Manufacturer_Name=CTS, Mouser Part Number=774-218-4LPSTJ
U1 U2: "PWM Chopper Type DC Brushed Motor Driver"
U3: "ARM Cortex-M3 32-bit MCU, 128 KB Flash, 20 KB Internal RAM, 37 I/Os, 48-pin LQFP, -40 to 85 degC, Tray", I/Os (High Current)=37, Operating Frequency(F) (Processor speed) (MHz)=72, Supplier Part Number 1=497-6288-ND, Supply Voltage(Vcc) min (V)=2
U5: Manufacturer="Texas Instruments", Manufacturer Part Number=SN65HVD232DR, Operating Temperature="-40癈 ~ 85癈", Package / Case="8-SOIC (0.154\", 3.90mm Width)", Supplier Device Package=8-SOIC, Supplier Part Number 1=296-26344-2-ND, Voltage - Supply="3 V ~ 3.6 V"
U6: "DC-DC"
U7: library part LP2992, "LDO"
U8: "Magnetic Position Sensor"
Y1: "Crystal"

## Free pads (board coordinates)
  rrect80% 1.524x1.924 hole 0.9: 6(4.242,28.562) 7(6.146,28.576) 8(19.539,28.657)
  oval 1.524x1.924 hole 0.9: 9(21.539,28.657)
  round 5.08 hole 3.1: ""(0,0) ""(0,26) ""(26,0) ""(26,26)

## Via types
v1: diameter 0.457, hole 0.254, Top1 to Bottom4, tented top, 108 vias
v2: diameter 0.6, hole 0.3, Top1 to Bottom4, tented both sides, 17 vias
v3: diameter 1.2, hole 0.6, Top1 to Bottom4, 3 vias

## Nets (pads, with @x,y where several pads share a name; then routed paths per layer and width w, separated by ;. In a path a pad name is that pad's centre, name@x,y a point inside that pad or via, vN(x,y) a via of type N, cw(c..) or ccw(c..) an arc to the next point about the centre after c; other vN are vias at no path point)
ADC_ENC: U3.16
AGND: C1.1 C2.1 C3.1 C4.1 C5.1 C23.1 R5.1 R22.2 U3.8 | length 28.2
  Top1 w0.3: C2.1 2.55,14.544 2.55,13.745 R22.2 3.041,13.254 3.231,13.254 C1.1 4.265,13.231 5.438,13.231 C4.1 6.454,13.236 7.334,13.236 7.383,13.284 v1(8.306,13.284) ; U3.8 10.491,7.863 11.927,7.863 C23.1 v1(12.598,7.899)
  Top1 w0.5: v1(8.306,13.284) 8.306,13.716 C5.1 ; v1(17.374,13.462) 17.297,13.538 17.297,14.046 R5.1
  Gnd3 w0.3: v1(8.306,13.284) 8.791,12.799 8.791,11.529 11.924,8.396 12.101,8.396 v1(12.598,7.899) 14.021,7.899 15.748,9.627 15.748,11.43 17.059,12.741 17.059,13.105 17.374,13.42 v1(17.374,13.462)
BUTTON_1: K1.2 U3.25 | length 1.9
  Top1 w0.2: K1.2 0.718,9.862 U3.25
BUTTON_2: K2.2 U3.20 | length 8.8
  Top1 w0.2: K2.2 0.381,7.552 v1(0.4,7.571) ; U3.20 5.549,10.25 v1@5.563,10.236
  Bottom4 w0.2: v1(0.4,7.571) 1.642,7.571 4.314,10.243 v1(5.556,10.243)
CAN_H: P1.6 P2.6 R12.1 U5.7 | length 88.4
  Top1 w0.2: R12.1 12.903,-3.353 13.818,-2.438 13.818,-1.473 13.689,-1.344 13.427,-1.344 v1(13.384,-1.301)
  Signal2 w0.2: v1(13.384,-1.301) 13.415,-1.27 13.716,-1.27 13.919,-1.067 13.919,-0.813 14.3,-0.432 18.212,-0.432 21.031,-3.251 27.285,-3.251 29.505,-1.031 29.505,22.469 29.088,22.885 24.613,22.885 20.799,26.699 18.082,26.699 17.018,27.762 16.256,27.762 16.053,27.559 16.053,27.178 16.358,26.873 P1.6@16.358,26.721
  Bottom4 w0.18: v1(13.384,-1.301) 13.411,-1.328 U5.7
  Bottom4 w0.2: P1.6@16.51,26.924 16.205,27.229 16.205,27.666 16.429,27.889 18.065,27.889 24.587,21.367 24.587,14.378 26.141,12.824 P2.6
CAN_L: P1.5 P2.5 S1.5 U5.6 | length 88.2
  Top1 w0.2: v1(14.681,-1.295) 14.632,-1.345 14.276,-1.345 14.122,-1.499 14.122,-2.184 14.554,-2.616 S1.5
  Signal2 w0.2: v1(14.681,-1.295) 14.632,-1.246 14.327,-1.246 14.221,-1.14 14.221,-0.938 14.425,-0.733 18.031,-0.733 20.879,-3.581 27.381,-3.581 29.87,-1.092 29.87,22.53 29.213,23.187 24.794,23.187 20.98,27 18.364,27 17.272,28.092 16.129,28.092 15.723,27.686 15.723,27.426 15.179,26.882 P1.5
  Bottom4 w0.2: U5.6 v1(14.681,-1.295) ; P1.5@15.494,26.949 15.85,27.305 15.85,27.737 16.358,28.245 18.136,28.245 24.892,21.488 24.892,14.554 25.122,14.324 P2.5
CAN_RX: U3.45 U5.4 | length 11.1
  Top1 w0.18: U3.45 7.549,4.146 7.976,4.572 8.839,4.572 v1@9.068,4.801
  Bottom4 w0.18: v1(9.119,4.877) 10.477,4.877 11.008,4.346 15.416,4.346 15.89,3.871 15.89,3.067 U5.4
CAN_TX: U3.46 U5.1 | length 10.2
  Top1 w0.18: U3.46 8.049,3.985 8.23,4.166 v1@9.119,4.166
  Bottom4 w0.18: v1(9.195,4.216) 9.574,4.595 10.264,4.595 10.795,4.064 12.141,4.064 12.192,4.013 12.522,4.013 12.827,3.708 12.827,2.083 12.522,1.778 12.116,1.778 11.963,1.93 11.963,2.08 12.08,2.196 12.08,2.944 U5.1
GND: C6.1 C7.1 C8.1 C9.1 C10.1 C12.2 C13.2 C18.1 C19.1 C20.1 C21.1 C22.1 C24.1 C25.1 C36.1 D3.1 K1.1 K2.1 LED1.C LED2.C P3.1 P3.4 R9.2 R14.1 R20.1 R22.1 S1.6 S1.7 S1.8 U3.23 U3.35 U3.47 U5.2 U6.2 U7.2 U8.8 | length 34.5
  Top1 w0.3: U3.35 3.389,4.862 3.835,5.309 v1(4.674,5.309) ; U3.23 U3.23 4.05,10.352 v1(4.623,9.779) ; v1(7.645,1.651) 7.798,1.803 8.026,1.803 8.207,1.984 8.217,1.984 8.453,2.22 8.453,2.29 8.549,2.386 U3.47 ; C6.1 C36.1 ; v1(16.586,2.083) 16.586,1.159 ; S1.6 16.839,-1.346 16.725,-1.232 16.586,-1.093 16.586,-0.178 ; S1.7 16.688,-0.076 16.586,-0.178 ; S1.8 16.621,1.194 16.586,1.159 ; 16.586,-0.178 16.586,1.159
  Top1 w0.39: v1(-3.607,4.674) K2.1@-3.607,5.182 ; K2.1@-3.581,6.909 v1(-3.581,7.417) ; v1(-3.581,8.128) K1.1@-3.581,8.636 ; K1.1@-3.581,10.312 v1(-3.581,10.82) ; K1.1@-3.251,9.347 v1(-2.743,9.347) ; K2.1@-3.2,5.791 v1(-2.692,5.791) ; C7.1@1.804,11.666 v1(1.804,12.174) ; v1(2.032,12.7) 2.54,12.7 R22.1 ; v1(11.168,2.519) C10.1@11.168,3.027 ; C36.1@13.983,3.772 13.983,3.391 v1(13.995,3.378) ; v1(16.612,4.42) C12.2 ; v1(16.612,8.915) 16.612,8.357 C13.2@16.637,8.331
  Top1 w0.5: C8.1 v1(5.182,0.279) ; LED1.C 5.531,-3.454 v1@6.223,-3.454 ; v1(6.172,0.279) R9.2 ; v3@7.29,-1.422 7.29,-1.016 C9.1 ; S1.6 18.045,-1.357 19.264,-1.357 20.359,-2.452 20.359,-3.283 LED2.C
  Bottom4 w0.3: C25.1 C24.1 18.504,12.484 20.079,12.484 v3(20.168,12.395)
  Bottom4 w0.39: v1(13.411,2.057) U5.2@13.411,2.565
  Bottom4 w0.5: v1(9.122,13.712) 9.122,14.077 9.95,14.905 U8.8
  Bottom4 w0.6: v3(20.168,12.395) 20.282,12.51 21.738,12.51 R20.1@21.814,12.434
  other v1: 6.217,-3.454 19.253,2.769 18.034,3.277 17.755,4.547 26.06,5.055 27.153,5.41 17.729,6.223 27.356,6.502 27.305,7.341 17.729,7.645 17.729,8.179 17.729,8.712
  other v3: 7.137,-1.575
ID0: S1.1 U3.29 | length 17.8
  Top1 w0.18: U3.29 3.62,7.862 v1(3.658,7.899) ; S1.1@10.094,1.104 v1@11.606,1.104
  Bottom4 w0.18: v1(3.658,7.899) 4.424,7.133 4.424,5.897 3.226,4.699 3.226,4.089 4.57,2.745 5.84,2.745 8.026,0.559 8.451,0.559 8.454,0.555 10.258,0.555 10.844,1.142 v1(11.644,1.142)
ID1: S1.2 U3.30 | length 18.2
  Top1 w0.18: U3.30@1.661,7.353 v1@3.173,7.353 ; S1.2@10.145,-0.166 10.198,-0.113 v1(11.694,-0.113)
  Bottom4 w0.18: v1(3.211,7.39) 3.71,7.39 4.142,6.957 4.142,6.073 2.921,4.851 2.921,3.886 4.343,2.464 5.723,2.464 7.91,0.277 8.359,0.277 8.764,-0.128 11.679,-0.128 v1(11.694,-0.113)
ID2: S1.3 U3.31 | length 18.7
  Top1 w0.18: U3.31@2.068,6.845 v1@3.58,6.845 ; S1.3@10.17,-1.309 11.493,-1.309 12.04,-0.762 v1(12.04,-0.711)
  Bottom4 w0.18: v1(3.617,6.882) 3.861,6.638 3.861,6.248 2.639,5.027 2.639,3.711 4.168,2.182 5.607,2.182 7.814,-0.025 8.179,-0.025 8.865,-0.711 v1(12.04,-0.711)
IN_AM: U1.2 U3.14 | length 17.5
  Top1 w0.3: v1(8.026,9.627) 8.549,10.149 U3.14 ; U1.2 16.853,17.014 16.853,15.835 v1(16.866,15.822)
  Bottom4 w0.3: v1(8.026,9.627) 7.984,9.627 7.905,9.705 7.846,9.705 7.442,10.109 7.442,13.107 10.236,15.9 13.49,15.9 13.569,15.822 v1(16.866,15.822)
IN_AP: U1.3 U3.15 | length 19.3
  Top1 w0.3: v1(6.985,9.931) 7.015,9.961 7.523,9.961 8.049,10.488 U3.15 ; v1(18.11,15.85) U1.3
  Bottom4 w0.3: v1(6.985,9.931) 6.985,13.411 9.876,16.302 17.302,16.302 17.753,15.852 18.108,15.852 v1(18.11,15.85)
IN_BM: U2.2 U3.12 | length 8.9
  Top1 w0.3: v1(9.271,12.37) 9.271,13.106 9.911,13.746 9.911,15.448 10.757,16.294 10.757,16.988 U2.2 ; v1(9.474,9.881) 9.493,9.862 U3.12
  Bottom4 w0.3: v1(9.271,12.37) 9.271,10.126 9.474,9.923 v1(9.474,9.881)
IN_BP: U2.3 U3.13 | length 7.6
  Top1 w0.3: U3.13 9.5,11.303 10.312,12.116 10.312,15.282 10.804,15.773 11.43,15.773 12.027,16.37 12.027,16.988 U2.3
IN_PWM_A: R1.1 U3.22 | length 1.5
  Top1 w0.254: U3.22 4.559,11.313 4.559,12.23 4.75,12.421 4.75,12.675 R1.1
IN_PWM_B: R6.1 U3.21 | length 2.9
  Top1 w0.254: U3.21 5.059,11.313 5.059,12.053 5.223,12.217 6.375,12.217 R6.1
MT6816_AUX_CS: U3.17
MT6816_CS: U3.38 U8.1 | length 20.4
  Top1 w0.18: U3.38 4.069,2.941 4.069,4.476 v1(4.115,4.521) ; v1(11.963,9.957) 12.294,10.287 14.98,10.287 15.773,11.08 15.773,13.737 15.951,13.914 15.951,14.273 v1(16.004,14.326)
  Bottom4 w0.18: v1(4.115,4.521) 4.14,4.496 6.49,4.496 11.951,9.957 v1(11.963,9.957) ; U8.1 15.928,14.905 16.076,14.757 15.982,14.757 15.982,14.347 v1(16.004,14.326)
NetC1_2: C1.2 R1.2 R2.1 | length 2
  Top1 w0.3: C1.2 R1.2 4.803,13.845 4.803,13.947 R2.1
NetC4_2: C4.2 R6.2 R7.1 | length 1.9
  Top1 w0.254: R7.1 6.248,14.046 C4.2 R6.2
NetC9_2: C9.2 R10.1 U3.7 | length 9.8
  Top1 w0.2: C9.2 R10.1 8.658,0.479 8.658,1.223 v3(8.782,1.347) ; v1(9.322,6.655) 9.371,6.704 9.371,6.933 9.78,7.342 10.47,7.342 U3.7
  Bottom4 w0.3: v3(8.782,1.347) 8.782,1.353 7.95,2.184 7.95,5.283 v1(9.322,6.655)
NetC12_1: C12.1 R19.2 U3.5 Y1.1 | length 7
  Top1 w0.18: U3.5 11.494,6.362 11.684,6.172 11.874,6.172 R19.2 11.989,6.077 12.339,6.426 14.366,6.426 15.157,5.635 Y1.1 15.591,5.944 C12.1
NetC13_1: C13.1 R19.1 U3.6 Y1.3 | length 7.1
  Top1 w0.2: U3.6 11.383,6.862 11.582,7.061 11.938,7.061 R19.1 13.065,7.093 Y1.3@13.557,7.585 ; Y1.3 Y1.3@13.557,7.585 ; C13.1 16.053,6.756 14.386,6.756 Y1.3@13.557,7.585
NetC15_1: C15.1 C17.1 D3.2 L1.1 U6.6
NetC15_2: C15.2 C17.2 U6.1
NetC16_2: C16.2 R13.1 R14.2 U6.3
NetC20_2: C20.2 D4.2 R15.1 U6.5
NetC23_2: C23.2 R21.1 U3.9 | length 2.8
  Top1 w0.3: U3.9 11.41,8.362 C23.2 12.039,8.991 12.344,8.991 R21.1
NetLED1_A: LED1.A R11.2 | length 1.8
  Top1 w0.16: LED1.A 3.912,-3.35 4.572,-2.69 4.572,-2.032 R11.2
NetLED2_A: LED2.A R18.2 | length 1.5
  Top1 w0.16: R18.2 21.615,-3 LED2.A
NetR3_1: R3.1 U1.7 | length 1.9
  Top1 w0.5: U1.7 v2@16.84,23.266
  Bottom4 w0.5: R3.1@16.846,24.232 16.856,24.222 16.856,23.276 v2(16.866,23.266)
NetR8_1: R8.1 U2.7 | length 2.2
  Top1 w0.5: v2@10.414,23.216 v2(10.414,23.19) 10.414,23.108 10.795,22.727 U2.7
  Bottom4 w0.5: R8.1@10.256,24.232 10.395,24.093 10.395,23.209 v2(10.414,23.19)
NetR9_1: R9.1 U3.44 | length 1.9
  Top1 w0.2: R9.1@6.756,1.168 6.894,1.306 6.894,1.424 6.909,1.44 6.909,1.651 7.049,1.791 U3.44
NetR12_2: R12.2 S1.4 | length 1.9
  Top1 w0.2: R12.2 8.651,-2.337 8.93,-2.616 S1.4
NetR15_2: R15.2 U6.4 | length 2
  Top1 w0.3: U6.4 23.908,8.855 24.106,9.053 24.106,9.34 24.458,9.691 24.458,10.208 R15.2
OUT_A+: pad.9 U1.6 | length 7.8
  Top1 w1: U1.6 18.11,23.419 21.424,26.732 21.424,28.542 pad.9
OUT_A-: pad.8 U1.8 | length 8.6
  Top1 w1: U1.8@15.57,22.477 15.57,23.927 16.51,24.867 17.831,24.867 19.424,26.46 19.424,28.542 pad.8
OUT_B+: pad.7 U2.6 | length 10.3
  Top1 w1: pad.7@6.146,28.657 6.146,28.495 7.675,26.966 7.675,25.912 8.822,24.765 11.405,24.765 12.116,24.054 12.116,22.377 U2.6
OUT_B-: pad.6 U2.8 | length 9
  Top1 w1: pad.6 4.242,26.806 5.495,25.552 6.477,25.552 9.525,22.504 U2.8
PC13: R11.1 U3.2 | length 23.6
  Top1 w0.16: R11.1 v1(5.258,-0.889) ; U3.2 v1(11.796,4.862) v1@11.811,4.877
  Bottom4 w0.16: v1(5.258,-0.889) 5.258,-1.524 6.35,-2.616 10.033,-2.616 11.481,-1.168 12.217,-1.168 12.564,-0.822 12.564,0.946 11.681,1.829 11.532,1.829 11.405,1.956 9.373,1.956 8.509,2.819 8.509,5.105 8.915,5.512 11.146,5.512 v1(11.796,4.862)
PC14: R18.1 U3.3 | length 14.9
  Top1 w0.16: U3.3 12.173,5.362 13.065,4.47 15.735,4.47 17.12,3.086 17.12,2.388 17.45,2.057 19.736,2.057 21.615,0.178 R18.1
PC15: U3.4
PGND: C11.2 C27.1 C28.1 C29.2 C30.2 C31.2 C32.2 D2.1 P1.3 P1.4 P2.3 P2.4 R3.2 R8.2 R20.2 U1.1 U1.9 U2.1 U2.9
  other v1: 6.883,16.459 3.835,16.561 6.909,17.297 3.937,17.399 6.858,18.009 3.937,18.186 6.934,18.669 3.988,18.872
  other v2: 10.637,18.954 11.475,18.954 12.313,18.954 16.656,18.98 17.495,18.98 18.333,18.98 10.637,20.021 11.449,20.021 12.262,20.021 16.656,20.047 17.469,20.047 18.282,20.047
POWER_U: U3.10
SPI1_MISO: U3.40 U8.6 | length 13.6
  Top1 w0.18: U3.40 5.049,3.881 5.766,4.597 5.766,5.156 v1(6.274,5.664)
  Bottom4 w0.18: v1(6.274,5.664) 8.865,8.255 8.865,10.228 8.384,10.708 8.384,12.37 8.804,12.79 9.31,12.79 9.322,12.802 9.513,12.802 9.95,12.365 U8.6
SPI1_MOSI: U3.41 U8.5 | length 10.3
  Top1 w0.18: U3.41 5.549,3.924 6.274,4.648 v1(6.274,4.978)
  Bottom4 w0.18: v1(6.274,4.978) 10.04,8.745 10.04,11.025 10.11,11.095 U8.5
SPI1_SCK: U3.39 U8.7 | length 14.2
  Top1 w0.18: U3.39 4.549,4.117 5.309,4.877 5.309,5.385 v1(6.35,6.426)
  Bottom4 w0.18: v1(6.35,6.426) 8.583,8.659 8.583,10.111 8.103,10.592 8.103,12.487 8.699,13.083 9.398,13.083 9.95,13.635 U8.7
SPI2_MISO: U3.27
SPI2_MOSI: U3.28
SPI2_SCK: U3.26
SWCLK: P3.2 U3.37 | length 16
  Top1 w0.2: P3.2 -1.012,14.324 -2.057,13.279 -2.057,6.121 0.102,3.962 1.448,3.962 2.056,3.354 3.501,3.354 3.549,3.306 U3.37
SWDIO: P3.3 U3.34 | length 15
  Top1 w0.2: P3.3 -0.512,15.824 0.24,15.073 0.24,11.873 -1.092,10.541 -1.092,5.69 -0.305,4.902 1.114,4.902 1.574,5.362 U3.34
TEMP: C3.2 R4.1 R5.2 U3.11 | length 16.5
  Top1 w0.152: R4.1 14.548,17.557 14.828,17.557 15.113,17.272 15.113,16.479 15.463,16.129 15.507,16.129 15.786,15.85 16.129,15.85 C3.2 R5.2
  Top1 w0.18: U3.11 12.041,9.362 12.407,9.728 12.407,9.759 12.654,10.005 15.187,10.005 16.256,11.074 16.256,11.633 18.276,13.654 18.276,14.54 18.263,14.554 18.263,14.63 R5.2
UART1_RX: P3.6 U3.43 | length 22.6
  Top1 w0.2: P3.6 -0.756,20.324 -0.236,19.805 -0.236,19.798 0.991,18.572 0.991,11.125 1.27,10.846 2.743,10.846 5.411,8.178 6.503,8.178 6.604,8.077 7.315,7.366 7.315,4.679 6.549,3.913 U3.43
UART1_TX: P3.5 U3.42 | length 21.6
  Top1 w0.2: P3.5 0.276,18.824 0.66,18.44 0.66,12.675 0.686,12.649 0.686,10.998 1.14,10.544 2.613,10.544 5.281,7.877 6.378,7.877 7.014,7.241 7.014,4.804 6.049,3.839 U3.42
USB_DM: U3.32
USB_DP: U3.33
VCC: C11.1 C27.2 C28.2 C29.1 C30.1 C31.1 C32.1 D1.2 D2.2 D4.1 U1.5 U2.5
  other v1: 21.717,15.545 21.107,15.596 20.777,16.129 20.701,17.018 20.701,17.78 13.36,21.031 19.917,21.06 6.528,21.082 19.202,21.082 3.988,21.107 4.699,21.107 5.486,21.133 7.087,21.412 19.583,21.488 13.894,21.514 3.785,21.717 7.137,22.073 14.173,22.073 3.962,22.504 6.96,22.86 4.115,23.089
VCC_3V3: C6.2 C7.2 C8.2 C10.2 C21.2 C22.2 C24.2 C25.2 C36.2 R4.2 R10.2 R21.2 T2.0 U3.1 U3.24 U3.36 U3.48 U5.3 U7.5 U8.2 U8.4 | length 22.9
  Top1 w0.2: R4.2 15.113,15.977 15.113,15.951 15.699,15.365 15.699,15.362 15.72,15.342 16.078,15.342 16.434,14.986 16.434,13.513 16.579,13.368 v1(16.579,13.147)
  Top1 w0.35: C8.2 4.572,1.27 v1(5.105,1.27) ; v1(8.534,-1.194) R10.2 ; U3.48 9.049,3 9.072,3.023 C10.2 ; v1@10.135,2.362 v1(10.16,2.388) C10.2 ; C6.2 11.961,4.067 11.453,4.067 11.176,4.343 10.509,4.343 U3.1 10.183,4.362 10.16,4.339 C10.2 ; R21.2 v1(14.402,9.5)
  Top1 w0.39: v1(0.787,4.394) 0.82,4.362 U3.36 ; v1@2.769,12.09 C7.2 2.828,11.549 3.507,11.549 3.549,11.506 U3.24 ; v1(14.732,2.057) 14.732,2.076 14.884,2.228 C36.2
  Bottom4 w0.35: U8.4 16.091,11.095 16.578,11.582 16.637,11.582 16.739,11.684 C25.2 ; U8.2 16.091,13.635 v1(16.579,13.147) 16.825,13.147 C24.2 C25.2 ; v1(17.272,10.744) 17.272,10.773 17.399,10.9 C25.2
  Bottom4 w0.39: v1(14.732,2.057) U5.3@14.732,2.565
  other v1: 17.018,10.033 17.729,10.185 16.637,10.439 2.769,12.065
VCC_5V: C16.1 C18.2 C19.2 L1.2 R13.2 U7.1 U7.3 | length 10.4
  Top1 w0.3: v1(28.016,4.14) 28.042,4.166 R13.2 C16.1
  Bottom4 w0.3: v2(21.514,4.547) 21.92,4.14 v1(28.016,4.14)
  other v2: 20.777,4.547 20.345,5.131
VCC_IN: D1.1 P1.1 P1.2 P2.1 P2.2
VREF_A: C2.2 R2.2 U1.4 | length 20
  Top1 w0.254: R2.2 C2.2 4.089,15.088 7.671,15.088 v1(7.772,15.189)
  Top1 w0.3: v1(19.355,15.9) 19.367,15.913 19.367,17.014 U1.4
  Bottom4 w0.3: v1(7.772,15.189) 7.772,15.232 8.174,15.634 8.174,15.958 9.321,17.105 12.432,17.105 12.929,17.602 14.148,17.602 14.961,16.789 18.059,16.789 18.948,15.9 v1(19.355,15.9)
VREF_B: C5.2 R7.2 U2.4 | length 8.4
  Top1 w0.3: R7.2 C5.2 8.721,15.147 8.684,15.184 8.684,15.73 v1(8.654,15.76) ; U2.4 13.365,16.997 13.737,16.997 v1(13.767,16.967)
  Bottom4 w0.3: v1(8.654,15.76) 9.598,16.704 12.69,16.704 12.954,16.967 v1(13.767,16.967)
pads on no net: U3.18 U3.19 U5.5 U5.8 U7.4 U8.3 Y1.2 Y1.4

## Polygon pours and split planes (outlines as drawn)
PGND on Top1 "NONET_L01_P-001" (solid, pour order 114): 20.879,12.821 20.879,13.106 22.174,14.402 23.571,14.402 24.181,15.011 24.181,17.628 24.613,18.059 28.169,18.059 28.372,17.856 28.372,15.342 28.219,15.189 25.527,15.189 25.375,15.037 25.375,11.227 25.095,10.947 21.031,10.947 20.828,11.151 20.828,13.005 21.006,13.183
PGND on Top1 "NONET_L01_P-001" (solid, pour order 112): 11.481,25.781 11.481,27.584 11.811,27.915 14.3,27.915 14.453,27.762 14.453,24.435 14.326,24.308 12.954,24.308 12.852,24.409
VCC on Top1 "VCC_L01_P092" (solid, pour order 92): 18.466,15.367 20.574,15.367 20.853,15.088 20.853,13.767 20.726,13.64 18.415,13.64 18.288,13.767 18.288,15.189
NetC20_2 on Top1 "NETC20_2_L01_P093" (solid, pour order 93): 19.71,13.056 19.71,10.77 19.99,10.49 22.758,10.49 22.936,10.668 23.948,10.668 24.054,10.562 24.054,9.728 23.851,9.525 22.987,9.525 22.758,9.296 22.758,8.484 22.885,8.357 24.333,8.357 24.486,8.204 24.486,7.468 24.435,7.417 22.733,7.417 22.276,7.874 20.637,7.874 20.142,8.369 20.142,9.398 19.787,9.754 18.339,9.754 18.059,10.033 18.059,12.954 18.237,13.132 19.634,13.132
VCC_5V on Top1 "VCC_5V_L01_P098" (solid, pour order 98): 20.142,5.918 22.377,5.918 22.53,5.766 22.53,3.988 21.895,3.353 20.142,3.353 19.964,3.531 19.964,5.74
NetC16_2 on Top1 "NETC16_2_L01_P096" (solid, pour order 96): 25.019,9.601 25.222,9.804 29.616,9.804 29.743,9.677 29.743,6.325 29.718,6.299 28.804,6.299 28.651,6.452 28.651,9.119 28.55,9.22 27.178,9.22 27.051,9.093 27.051,8.509 26.975,8.433 25.197,8.433 25.019,8.611 25.019,8.687
GND on Top1 "GND_L01_P095" (solid, pour order 95): 17.704,9.627 17.348,9.271 17.348,2.718 17.678,2.388 22.047,2.388 22.301,2.642 22.987,2.642 23.851,3.505 24.765,3.505 25.121,3.861 27.356,3.861 27.686,4.191 27.686,8.179 27.483,8.382 25.222,8.382 25.095,8.255 25.095,7.62 25.197,7.518 26.797,7.518 26.949,7.366 26.949,6.274 26.518,5.842 25.629,5.842 25.324,5.537 25.324,4.42 25.044,4.14 22.936,4.14 21.996,3.2 20.066,3.2 19.837,3.429 19.837,5.321 19.672,5.486 18.567,5.486 18.313,5.74 18.313,7.62 18.542,7.849 19.583,7.849 19.761,8.026 19.761,9.525 19.66,9.627 19.355,9.627
VCC on Top1 "VCC_L01_P091" (solid, pour order 91): 23.52,18.11 23.622,18.009 23.622,15.088 23.419,14.884 20.168,14.884 20.041,15.011 20.041,17.983 20.168,18.11 20.523,18.11
NetC15_1 on Top1 "NETC15_1_L01_P073" (solid, pour order 73): 23.089,4.851 22.758,5.182 22.758,6.045 22.581,6.223 18.796,6.223 18.491,6.528 18.491,7.518 18.694,7.722 20.752,7.722 20.955,7.518 22.25,7.518 22.454,7.315 24.282,7.315 24.384,7.214 24.384,6.274 23.876,5.766 23.876,4.267 23.8,4.191 23.292,4.191 23.089,4.394
PGND on Top1 "PGND_L01_P088" (solid, pour order 88): 7.849,19.456 7.849,20.345 7.976,20.472 20.32,20.472 20.422,20.371 20.422,18.415 20.32,18.313 16.129,18.313 16.027,18.212 16.027,16.281 15.875,16.129 15.138,16.129 14.961,16.307 14.961,18.186 14.808,18.339 10.135,18.339 10.033,18.237 10.033,16.307 9.855,16.129 7.696,16.129 7.595,16.231 7.798,16.434 7.798,19.406
PGND on Top1 "PGND_L01_P089" (solid, pour order 89): 21.59,23.419 21.717,23.292 21.717,20.65 21.539,20.472 20.244,20.472 20.193,20.422 20.193,18.44 20.32,18.313 22.377,18.313 22.758,18.694 22.758,24.105 22.403,24.46 20.32,24.46 20.041,24.181 20.041,23.444 20.066,23.419
PGND on Top1 "PGND_L01_P083" (solid, pour order 83): 2.921,19.456 7.849,19.456 7.976,19.329 7.976,15.951 7.645,15.621 3.073,15.621 2.591,16.104 2.591,19.126
VCC on Top1 "VCC_L01_P081" (solid, pour order 81): 3.632,24.486 6.274,24.486 7.518,23.241 7.518,20.091 7.391,19.964 3.099,19.964 2.616,20.447 2.616,22.936 3.632,23.952 3.632,24.511
NetC15_2 on Top1 "NETC15_2_L01_P074" (solid, pour order 74): 23.952,5.486 23.952,5.639 24.714,6.401 24.714,7.112 25.019,7.417 26.746,7.417 26.848,7.315 26.848,6.477 26.695,6.325 25.603,6.325 25.019,5.74 25.019,4.369 24.917,4.267 24.028,4.267 23.952,4.343 23.952,5.626 24.041,5.715
VCC_3V3 on Signal2 "VCC_3V3_L02_P110" (solid, pour order 110): -4.547,22.225 1.118,22.225 1.499,21.844 1.499,15.342 1.676,15.164 7.112,15.164 8.179,16.231 19.66,16.231 20.879,15.011 20.879,10.719 21.133,10.465 28.854,10.465 28.981,10.338 28.981,3.835 28.499,3.353 24.13,3.353 22.784,2.007 17.069,2.007 16.311,1.249 10.19,1.249 9.246,0.305 9.246,-4.547 3.581,-4.547 2.896,-3.861 2.896,1.93 0.711,4.115 -4.597,4.115 -4.597,22.174
PGND on Signal2 "PGND_L02_P108" (solid, pour order 108): 8.018,20.549 21.514,20.549 21.793,20.269 21.793,18.618 21.488,18.313 8.128,18.313 7.957,18.484
VCC_IN on Signal2 "VCC_IN_L02_P076" (solid, pour order 76): 8.331,24.282 8.331,24.206 8.763,23.774 18.771,23.774 24.435,18.11 28.321,18.11 28.608,18.397 28.608,22.065 28.423,22.25 24.613,22.25 21.387,25.476 11.684,25.476 11.455,25.705 11.455,28.804 11.074,29.185 8.763,29.185 8.28,28.702 8.28,24.333
GND on Gnd3 "GND_L03_P109" (solid, pour order 109): -4.47,22.225 1.194,22.225 1.575,21.844 1.575,15.342 1.753,15.164 7.188,15.164 8.255,16.231 19.736,16.231 20.955,15.011 20.955,10.719 21.209,10.465 28.931,10.465 29.058,10.338 29.058,3.835 28.575,3.353 24.206,3.353 22.86,2.007 17.145,2.007 16.387,1.249 10.266,1.249 9.322,0.305 9.322,-4.547 3.658,-4.547 2.972,-3.861 2.972,1.93 0.787,4.115 -4.521,4.115 -4.521,22.174
PGND on Gnd3 "NONET_L01_P-001" (solid, pour order 113): 11.506,28.016 11.506,25.756 13.385,23.877 19.1,23.877 23.495,19.482 23.495,18.313 23.698,18.11 23.698,15.443 23.876,15.265 28.092,15.265 28.372,15.545 28.372,17.729 28.067,18.034 25.73,18.034 25.146,18.618 25.146,21.717 21.438,25.425 14.859,25.425 14.503,25.781 14.503,28.804 14.148,29.159 11.836,29.159 11.481,28.804 11.481,27.584
PGND on Gnd3 "PGND_L03_P107" (solid, pour order 107): 8.128,20.523 23.317,20.523 23.597,20.244 23.597,18.415 23.495,18.313 8.128,18.313 7.95,18.491 7.95,20.396 8.103,20.549
PGND on Bottom4 "NONET_L01_P-001" (solid, pour order 117): 24.892,13.614 25.298,13.208 25.298,12.09 25.4,11.989 27.254,11.989 27.584,12.319 27.584,15.037 27.381,15.24 25.654,15.24 25.324,15.57 25.324,17.882 25.552,18.11 29.82,18.11 30.251,17.678 30.251,10.897 29.947,10.592 24.054,10.592 23.368,11.278 23.368,13.36 23.622,13.614 24.003,13.614
PGND on Bottom4 "NONET_L01_P-001" (solid, pour order 111): 12.116,23.468 11.57,24.014 11.57,27.673 11.811,27.915 14.3,27.915 14.453,27.762 14.453,25.603 15.265,24.79 15.265,23.571 14.91,23.216 12.268,23.216 11.557,23.926 11.557,24.028
VCC_3V3 on Bottom4 "VCC_3V3_L04_P103" (solid, pour order 103): 18.339,8.915 18.339,9.55 18.11,9.779 16.281,9.779 16.053,10.008 16.053,10.541 16.561,11.049 19.025,11.049 19.685,10.389 21.184,10.389 21.387,10.185 21.387,8.763 21.234,8.611 18.644,8.611
VCC_5V on Bottom4 "VCC_5V_L04_P102" (solid, pour order 102): 24.257,8.687 24.435,8.509 24.435,7.671 24.206,7.442 22.911,7.442 21.311,5.842 20.117,5.842 19.888,5.613 19.888,4.293 20.168,4.013 22.149,4.013 22.504,4.369 22.504,4.851 24.943,7.29 24.943,8.855 24.282,9.516 22.996,9.516 22.987,9.525 22.758,9.296 22.758,8.839 22.911,8.687
GND on Bottom4 "GND_L04_P101" (solid, pour order 101): 18.669,8.509 18.491,8.509 18.11,8.89 18.11,9.423 18.059,9.474 17.348,9.474 17.145,9.271 17.145,7.391 17.45,7.087 19.329,7.087 19.685,7.442 19.583,7.544 19.583,8.204 18.974,8.204
GND on Bottom4 "GND_L04_P100" (solid, pour order 100): 24.181,8.509 24.333,8.357 24.333,7.696 24.206,7.569 18.491,7.569 18.263,7.798 18.263,8.213 18.559,8.509 18.961,8.509
VCC on Bottom4 "VCC_L04_P085" (solid, pour order 85): 22.276,22.657 22.835,22.657 24.155,21.336 24.155,15.545 23.876,15.265 20.676,15.265 20.422,15.519 20.422,17.856 20.549,17.983 22.557,17.983 22.733,18.159 22.733,20.168 21.869,21.031 21.869,21.996 21.895,22.022
PGND on Bottom4 "PGND_L04_P082" (solid, pour order 82): 22.098,20.447 22.276,20.269 22.276,18.542 22.098,18.364 8.255,18.364 8.077,18.186 8.077,16.535 7.163,15.621 3.454,15.621 2.972,16.104 2.972,19.939 3.48,20.447
VCC on Bottom4 "VCC_L04_P080" (solid, pour order 80): 4.479,23.492 8.969,23.492 9.804,22.657 22.276,22.657 22.403,22.53 22.403,20.93 22.174,20.701 3.48,20.701 3.15,21.031 3.15,23.114 3.505,23.47 4.456,23.47
VCC_IN on Bottom4 "VCC_IN_L04_P079" (solid, pour order 79): 11.354,25.552 8.357,25.552 8.204,25.4 8.204,24.333 7.95,24.079 4.343,24.079 4.115,24.308 4.115,27.28 4.394,27.559 11.151,27.559 11.354,27.356 11.354,25.578

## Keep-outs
Keep-Out Layer:
  lines w0.254: -0.003,30.511 25.959,30.511 ; 0.048,-4.516 26.01,-4.516

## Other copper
Top1:
  rectangle net GND: 27.635,8.484 28.423,9.093
  rectangle net GND: 27.356,8.179 27.762,9.093
  rectangle net VCC: 18.999,20.853 21.361,23.241
  rectangle net VCC: 12.852,20.701 14.503,24.079
  pour cut-out: 10.947,15.242 10.947,10.615 14.935,10.615 14.935,15.242
  text "L1" at -3.916,2.637 h0.99
Signal2:
  pour cut-out: 10.795,15.443 10.795,10.363 15.367,10.363 15.367,15.443
  text "L2" at -3.993,2.992 h0.99
Gnd3:
  pour cut-out: 10.714,15.5 10.714,10.42 15.286,10.42 15.286,15.5
  text "L3" at -3.916,2.637 h0.99
Bottom4:
  rectangle net PGND: 3.302,18.364 22.047,20.371
  pour cut-out: 10.77,15.545 10.77,10.465 15.342,10.465 15.342,15.545
  text "L4" at -3.891,2.865 h0.99

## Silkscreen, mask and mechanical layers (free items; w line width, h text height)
Top Overlay:
  lines w0.254: 24.409,4.496 24.633,4.272 26.564,4.272 26.187,4.648 27.61,4.648
  text "+" at 6.35,30.607 h5.08 r270
  text "24V" at 10.042,28.579 h1.8
  text "IN" at 13.623,27.656 h2
  text "B-B+" at 3.676,24.34 h1.5
  text "A-A+" at 18.725,24.276 h1.5
  text "+" at 27.254,22.835 h5.08 r270
  text "24V" at 28.579,19.346 h1.8 r270
  text "SCLK DIO" at -1.708,11.024 h1.14 r90
  text "V1.01" at 23.444,2.667 h1.52
Bottom Overlay:
  text "Designed by            MUZI XIAOWEN" at 15.629,5.106 h2
Bottom Solder:
  rectangle: 3.302,18.364 22.047,20.371
Mechanical 1:
  lines w0.254: -4.551,26.06 -4.551,26.564 cw(c-1.485,26.564) -3.653,28.732 -2.723,29.662 cw(c-0.555,27.494) -0.555,30.56 -0.051,30.56 ; -4.5,26 -4.5,0 -4.5,-0.504 ccw(c-1.434,-0.504) -3.602,-2.672 -2.672,-3.602 ccw(c-0.504,-1.434) -0.504,-4.5 0,-4.5 ; -0.003,30.511 25.984,30.511 ; 0.048,-4.516 25.908,-4.516 ; 25.984,-4.525 26.405,-4.525 ; 25.984,30.51 26.488,30.51 cw(c26.488,27.444) 28.656,29.612 29.586,28.681 cw(c27.418,26.513) 30.484,26.513 30.484,26.01 ; 26.405,-4.551 ccw(c26.405,-1.22) 28.76,-3.575 29.612,-2.748 ccw(c27.444,-0.58) 30.51,-0.58 30.51,-0.076 30.51,25.984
